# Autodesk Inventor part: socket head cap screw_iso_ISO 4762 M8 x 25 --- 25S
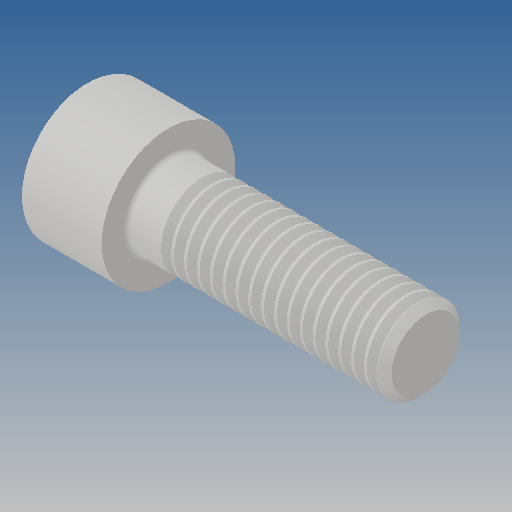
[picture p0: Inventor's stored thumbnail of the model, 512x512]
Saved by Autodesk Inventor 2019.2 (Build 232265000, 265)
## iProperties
Created: 2013-10
Part Number: socket head cap screw_iso_ISO 4762 M8 x 25 --- 25S
Material: Ogólny
Document SubType Name: Modeling
Designer: CADENGINEERING4
Density: 1 g/cm^3
Appearance: Domyślna
Author: CADENGINEERING4
Revision Number: ÈÎºÎ
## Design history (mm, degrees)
feature "ThdSchPat"
node "Bryła1"
